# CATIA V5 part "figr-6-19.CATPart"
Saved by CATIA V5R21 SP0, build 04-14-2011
Part number: Part1
Bounding box of the stored display mesh (mm): x 0 to 150, y -70 to 70, z -150 to 69.804
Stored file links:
  D:\CATIA V5R21 E-RESOURCES\CATIA-V5R21\catia-v5r21-prt\c06-catia-v5r21-prt\c06-catia-v5r21-figr-6-19.CATPart
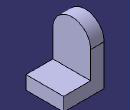
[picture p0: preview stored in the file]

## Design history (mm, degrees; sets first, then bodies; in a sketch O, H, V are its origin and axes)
Body1 (main body)
  Sketch1 on yz-plane, origin (0, 0, 0), H (0, 1, 0), V (0, 0, 1)
    arc A1 centre (0, 0) radius 70 from (70, 0) to (-70, 0) ccw
    point P1 (70, 0)
    point P2 (-70, 0)
    line L1 (-70, 0) -> (-70, -150)
    line L2 (-70, -150) -> (70, -150)
    line L3 (70, -150) -> (70, 0)
    construction circle A2 centre (0, 0) radius 37.5
    radius A1 = 70
    radius A2 = 37.5
    distance O L2 = 150
    coincidence: P1 H, P2 H
    tangency: L1 A1, L3 A1
    horizontal: L2 H
  Pad1: profile Sketch1, direction (1, 0, 0), length 50
  Sketch2 on face of Pad1, origin (50, 0, 0), H (0, 1, 0), V (0, 0, 1)
    line L1 (-70, -150) -> (70, -150)
    line L2 (70, -150) -> (70, -100)
    line L3 (70, -100) -> (-70, -100)
    line L4 (-70, -100) -> (-70, -150)
    reference projected line E1 (-70, -150) -> (70, -150) from edge [face of Pad1 | face of Pad1]
    reference projected line E2 (-70, 0) -> (-70, -150) from edge [face of Pad1 | face of Pad1]
    reference projected line E3 (70, -150) -> (70, 0) from edge [face of Pad1 | face of Pad1]
    length L2 = 50
    horizontal: L1 H, L3 H
    vertical: L2 V, L4 V
    coincidence: L1 E1, E2 L4, L2 E3
  Pad2: profile Sketch2, direction (1, 0, 0), length 100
